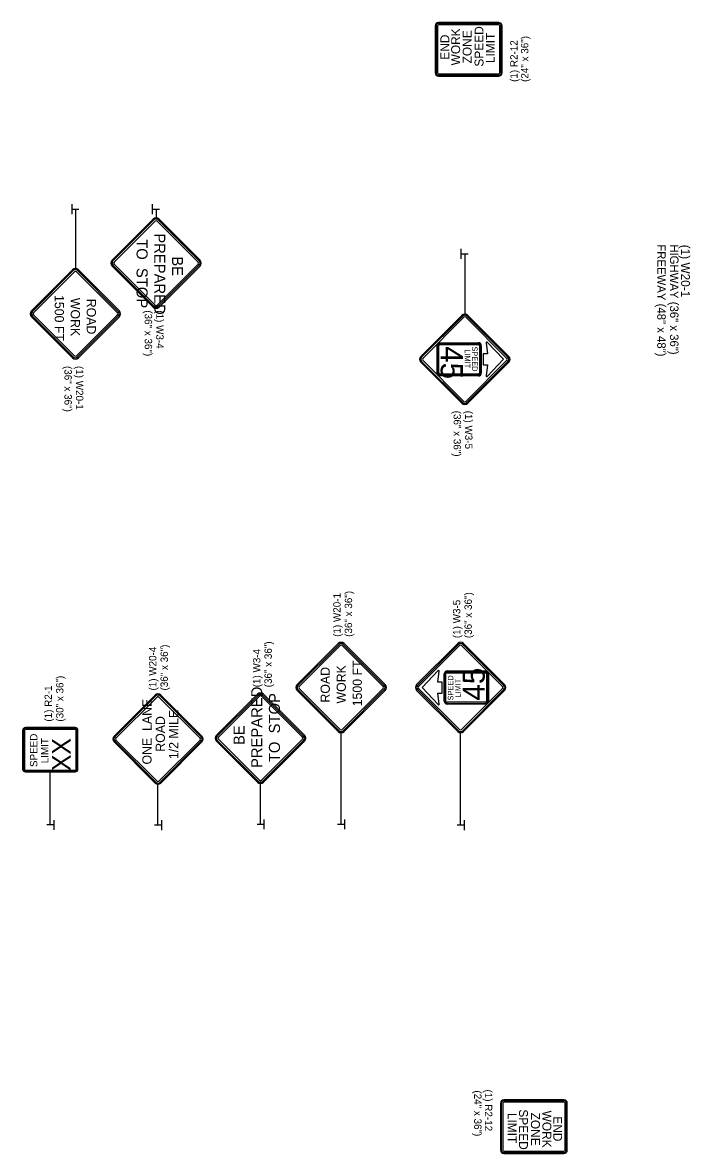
# Model space of a CAD drawing. Extents: x 1925873 to 1930787, y 596452 to 599617.
# Drawn here: x 1927188 to 1927732, y 598697 to 599617 of the extents above; entities that cross this region are included whole.
import ezdxf

# ---------------------------------------------------------------- set-up
doc = ezdxf.new("R2010")
doc.units = 0
for name, color, linetype in [('Default', 7, 'Continuous'), ('P_TC_Signs_Permanent', 7, 'Continuous'), ('P_TC_Signs_Temporary', 7, 'Continuous'), ('R_Border', 7, 'Continuous')]:
    doc.layers.add(name, color=color, linetype=linetype)

msp = doc.modelspace()

# ---------------------------------------------------------------- linework, layer by layer
at = {"layer": 'Default'}
for p, q in [((1927228.46, 599461.2), (1927228.46, 599469.2)), ((1927293.94, 599461.2), (1927293.94, 599469.2)), ((1927228.57, 599465.18), (1927234.04, 599465.18)), ((1927294.05, 599465.18), (1927299.52, 599465.18)), ((1927545.18, 599424.79), (1927545.18, 599432.79)), ((1927545.29, 599428.77), (1927550.76, 599428.77)), ((1927384.59, 598968.57), (1927384.59, 598960.56)), ((1927450.07, 598968.57), (1927450.07, 598960.56)), ((1927213.4, 598964.08), (1927207.93, 598964.08)), ((1927213.52, 598968.06), (1927213.52, 598960.05)), ((1927301.07, 598963.91), (1927295.6, 598963.91)), ((1927301.18, 598967.89), (1927301.18, 598959.89)), ((1927384.47, 598964.59), (1927379.01, 598964.59)), ((1927449.95, 598964.59), (1927444.49, 598964.59)), ((1927547.35, 598963.96), (1927541.88, 598963.96)), ((1927547.46, 598967.94), (1927547.46, 598959.93))]:
    msp.add_line(p, q, dxfattribs=at)
at = {"layer": 'P_TC_Signs_Permanent'}
for p, q in [((1927523.95, 599614.27), (1927523.95, 599576.2)), ((1927524.63, 599614.27), (1927524.63, 599576.2)), ((1927525.76, 599614.27), (1927525.76, 599576.2)), ((1927575.6, 599616.99), (1927526.67, 599616.99)), ((1927575.6, 599616.31), (1927526.67, 599616.31)), ((1927575.6, 599615.17), (1927526.67, 599615.17)), ((1927576.51, 599576.2), (1927576.51, 599614.27)), ((1927577.64, 599576.2), (1927577.64, 599614.27)), ((1927578.32, 599576.2), (1927578.32, 599614.27)), ((1927526.67, 599575.3), (1927575.6, 599575.3)), ((1927526.67, 599574.17), (1927575.6, 599574.17)), ((1927526.67, 599573.49), (1927575.6, 599573.49)), ((1927294.4, 599457.08), (1927260.99, 599423.67)), ((1927295.06, 599456.42), (1927261.65, 599423.01)), ((1927331.92, 599423.01), (1927298.51, 599456.42)), ((1927332.58, 599423.67), (1927299.17, 599457.08)), ((1927295.99, 599455.49), (1927262.58, 599422.08)), ((1927330.99, 599422.08), (1927297.58, 599455.49)), ((1927261.65, 599419.56), (1927295.06, 599386.15)), ((1927262.58, 599420.49), (1927295.99, 599387.08)), ((1927297.58, 599387.08), (1927330.99, 599420.49)), ((1927298.51, 599386.15), (1927331.92, 599419.56)), ((1927260.99, 599418.89), (1927294.4, 599385.48)), ((1927299.17, 599385.48), (1927332.58, 599418.89)), ((1927545.64, 599378.79), (1927512.23, 599345.38)), ((1927546.3, 599378.13), (1927512.89, 599344.72)), ((1927547.23, 599377.2), (1927513.82, 599343.79)), ((1927582.23, 599343.79), (1927548.82, 599377.2)), ((1927583.16, 599344.72), (1927549.75, 599378.13)), ((1927583.82, 599345.38), (1927550.41, 599378.79)), ((1927527.83, 599356.49), (1927559.03, 599356.49)), ((1927525.43, 599331.89), (1927525.43, 599354.09)), ((1927561.43, 599354.09), (1927561.43, 599331.89)), ((1927512.23, 599340.61), (1927545.64, 599307.2)), ((1927512.89, 599341.27), (1927546.3, 599307.86)), ((1927513.82, 599342.2), (1927547.23, 599308.79)), ((1927548.82, 599308.79), (1927582.23, 599342.2)), ((1927549.75, 599307.86), (1927583.16, 599341.27)), ((1927550.41, 599307.2), (1927583.82, 599340.61)), ((1927559.03, 599329.49), (1927527.83, 599329.49)), ((1927542.23, 599111.72), (1927508.82, 599078.31)), ((1927542.89, 599111.06), (1927509.48, 599077.65)), ((1927543.82, 599110.13), (1927510.41, 599076.72)), ((1927578.82, 599076.72), (1927545.41, 599110.13)), ((1927579.75, 599077.65), (1927546.34, 599111.06)), ((1927580.41, 599078.31), (1927547, 599111.72)), ((1927533.61, 599089.43), (1927564.81, 599089.43)), ((1927531.21, 599064.83), (1927531.21, 599087.03)), ((1927567.21, 599087.03), (1927567.21, 599064.83)), ((1927379.35, 599070.48), (1927345.94, 599037.06)), ((1927380.02, 599069.81), (1927346.6, 599036.4)), ((1927416.87, 599036.4), (1927383.46, 599069.81)), ((1927417.54, 599037.06), (1927384.13, 599070.48)), ((1927508.82, 599073.54), (1927542.23, 599040.13)), ((1927509.48, 599074.2), (1927542.89, 599040.79)), ((1927510.41, 599075.13), (1927543.82, 599041.72)), ((1927545.41, 599041.72), (1927578.82, 599075.13)), ((1927546.34, 599040.79), (1927579.75, 599074.2)), ((1927547, 599040.13), (1927580.41, 599073.54)), ((1927380.94, 599068.88), (1927347.53, 599035.47)), ((1927415.95, 599035.47), (1927382.53, 599068.88)), ((1927564.81, 599062.43), (1927533.61, 599062.43)), ((1927230.92, 599043.3), (1927190.42, 599043.3)), ((1927230.92, 599042.73), (1927190.42, 599042.73)), ((1927188.17, 599041.05), (1927188.17, 599009.55)), ((1927188.73, 599041.05), (1927188.73, 599009.55)), ((1927189.67, 599041.05), (1927189.67, 599009.55)), ((1927230.92, 599041.8), (1927190.42, 599041.8)), ((1927231.67, 599009.55), (1927231.67, 599041.05)), ((1927232.6, 599009.55), (1927232.6, 599041.05)), ((1927233.17, 599009.55), (1927233.17, 599041.05)), ((1927346.6, 599032.95), (1927380.02, 598999.54)), ((1927347.53, 599033.88), (1927380.94, 599000.47)), ((1927382.53, 599000.47), (1927415.95, 599033.88)), ((1927383.46, 598999.54), (1927416.87, 599032.95)), ((1927345.94, 599032.29), (1927379.35, 598998.88)), ((1927384.13, 598998.88), (1927417.54, 599032.29)), ((1927190.42, 599008.8), (1927230.92, 599008.8)), ((1927190.42, 599007.86), (1927230.92, 599007.86)), ((1927190.42, 599007.3), (1927230.92, 599007.3)), ((1927628.69, 598740.35), (1927579.75, 598740.35)), ((1927628.69, 598739.67), (1927579.75, 598739.67)), ((1927628.69, 598738.54), (1927579.75, 598738.54)), ((1927577.03, 598737.64), (1927577.03, 598699.57)), ((1927577.71, 598737.64), (1927577.71, 598699.57)), ((1927578.84, 598737.64), (1927578.84, 598699.57)), ((1927629.59, 598699.57), (1927629.59, 598737.64)), ((1927630.73, 598699.57), (1927630.73, 598737.64)), ((1927631.41, 598699.57), (1927631.41, 598737.64)), ((1927579.75, 598698.67), (1927628.69, 598698.67)), ((1927579.75, 598697.53), (1927628.69, 598697.53)), ((1927579.75, 598696.85), (1927628.69, 598696.85))]:
    msp.add_line(p, q, dxfattribs=at)
for points in [[(1927559.03, 599355.89), (1927527.83, 599355.89)], [(1927527.83, 599354.99), (1927559.03, 599354.99)], [(1927565.38, 599356.45), (1927566.5, 599347.49), (1927562.93, 599347.49), (1927562.93, 599338.49), (1927566.49, 599338.49), (1927565.38, 599329.61)], [(1927566.35, 599329.15), (1927579.43, 599343.03), (1927566.35, 599356.91)], [(1927526.03, 599354.09), (1927526.03, 599331.89)], [(1927526.93, 599331.89), (1927526.93, 599354.09)], [(1927559.93, 599354.09), (1927559.93, 599342.99), (1927559.93, 599331.89)], [(1927560.83, 599331.89), (1927560.83, 599342.99), (1927560.83, 599354.09)], [(1927559.03, 599330.99), (1927527.83, 599330.99)], [(1927527.83, 599330.09), (1927559.03, 599330.09)], [(1927526.29, 599089.77), (1927513.21, 599075.89), (1927526.29, 599062.01)], [(1927527.26, 599062.46), (1927526.14, 599071.43), (1927529.71, 599071.43), (1927529.71, 599080.43), (1927526.15, 599080.43), (1927527.26, 599089.31)], [(1927564.81, 599088.83), (1927533.61, 599088.83)], [(1927531.81, 599087.03), (1927531.81, 599075.93), (1927531.81, 599064.83)], [(1927532.71, 599064.83), (1927532.71, 599075.93), (1927532.71, 599087.03)], [(1927533.61, 599087.93), (1927564.81, 599087.93)], [(1927565.71, 599087.03), (1927565.71, 599064.83)], [(1927566.61, 599064.83), (1927566.61, 599087.03)], [(1927564.81, 599063.93), (1927533.61, 599063.93)], [(1927533.61, 599063.03), (1927564.81, 599063.03)]]:
    msp.add_lwpolyline(points, dxfattribs=at)
for centre, radius, start, end in [((1927526.67, 599614.27), 2.72, 90, 180), ((1927526.67, 599614.27), 2.04, 90, 180), ((1927526.67, 599614.27), 0.906, 90, 180), ((1927575.6, 599614.27), 2.72, 360, 90), ((1927575.6, 599614.27), 2.04, 360, 90), ((1927575.6, 599614.27), 0.906, 360, 90), ((1927526.67, 599576.2), 2.72, 180, 270), ((1927526.67, 599576.2), 2.04, 180, 270), ((1927526.67, 599576.2), 0.906, 180, 270), ((1927575.6, 599576.2), 2.72, 270, 360), ((1927575.6, 599576.2), 2.04, 270, 360), ((1927575.6, 599576.2), 0.906, 270, 360), ((1927296.79, 599454.69), 3.37, 45, 135), ((1927296.79, 599454.69), 2.44, 45, 135), ((1927296.79, 599454.69), 1.13, 45, 135), ((1927263.38, 599421.28), 3.37, 135, 225), ((1927263.38, 599421.28), 2.44, 135, 225), ((1927263.38, 599421.28), 1.13, 135, 225), ((1927330.2, 599421.28), 1.13, 315, 45), ((1927330.2, 599421.28), 2.44, 315, 45), ((1927330.2, 599421.28), 3.37, 315, 45), ((1927296.79, 599387.87), 3.37, 225, 315), ((1927296.79, 599387.87), 2.44, 225, 315), ((1927296.79, 599387.87), 1.13, 225, 315), ((1927548.03, 599376.4), 3.37, 45, 135), ((1927548.03, 599376.4), 2.44, 45, 135), ((1927548.03, 599376.4), 1.13, 45, 135), ((1927527.83, 599354.09), 2.4, 90, 180), ((1927527.83, 599354.09), 1.8, 90, 180), ((1927527.83, 599354.09), 0.9, 90, 180), ((1927559.03, 599354.09), 2.4, 360, 90), ((1927559.03, 599354.09), 1.8, 360, 90), ((1927559.03, 599354.09), 0.9, 360, 90), ((1927565.94, 599356.52), 0.563, 43.31166, 187.12501), ((1927514.62, 599342.99), 3.37, 135, 225), ((1927514.62, 599342.99), 2.44, 135, 225), ((1927514.62, 599342.99), 1.13, 135, 225), ((1927581.44, 599342.99), 1.13, 315, 45), ((1927581.44, 599342.99), 2.44, 315, 45), ((1927581.44, 599342.99), 3.37, 315, 45), ((1927527.83, 599331.89), 2.4, 180, 270), ((1927527.83, 599331.89), 1.8, 180, 270), ((1927527.83, 599331.89), 0.9, 180, 270), ((1927559.03, 599331.89), 2.4, 270, 360), ((1927559.03, 599331.89), 1.8, 270, 360), ((1927559.03, 599331.89), 0.9, 270, 360), ((1927565.94, 599329.54), 0.563, 172.87498, 316.68834), ((1927548.03, 599309.58), 3.38, 225, 315), ((1927548.03, 599309.58), 2.44, 225, 315), ((1927548.03, 599309.58), 1.13, 225, 315), ((1927544.61, 599109.34), 3.37, 45, 135), ((1927544.61, 599109.34), 2.44, 45, 135), ((1927544.61, 599109.34), 1.13, 45, 135), ((1927526.7, 599089.38), 0.563, 352.87498, 136.68834), ((1927533.61, 599087.03), 2.4, 90, 180), ((1927533.61, 599087.03), 1.8, 90, 180), ((1927564.81, 599087.03), 2.4, 360, 90), ((1927564.81, 599087.03), 1.8, 360, 90), ((1927533.61, 599087.03), 0.9, 90, 180), ((1927564.81, 599087.03), 0.9, 360, 90), ((1927381.74, 599068.09), 3.37, 45, 135), ((1927381.74, 599068.09), 2.44, 45, 135), ((1927511.2, 599075.93), 3.37, 135, 225), ((1927511.2, 599075.93), 2.44, 135, 225), ((1927511.2, 599075.93), 1.13, 135, 225), ((1927578.02, 599075.93), 1.13, 315, 45), ((1927578.02, 599075.93), 2.44, 315, 45), ((1927578.02, 599075.93), 3.37, 315, 45), ((1927381.74, 599068.09), 1.13, 45, 135), ((1927526.7, 599062.39), 0.563, 223.31166, 7.12501), ((1927533.61, 599064.83), 2.4, 180, 270), ((1927533.61, 599064.83), 1.8, 180, 270), ((1927533.61, 599064.83), 0.9, 180, 270), ((1927564.81, 599064.83), 2.4, 270, 360), ((1927564.81, 599064.83), 1.8, 270, 360), ((1927564.81, 599064.83), 0.9, 270, 360), ((1927190.42, 599041.05), 2.25, 90, 180), ((1927190.42, 599041.05), 1.69, 90, 180), ((1927230.92, 599041.05), 2.25, 360, 90), ((1927230.92, 599041.05), 1.69, 360, 90), ((1927190.42, 599041.05), 0.75, 90, 180), ((1927230.92, 599041.05), 0.75, 360, 90), ((1927348.33, 599034.68), 3.37, 135, 225), ((1927348.33, 599034.68), 2.44, 135, 225), ((1927348.33, 599034.68), 1.13, 135, 225), ((1927415.15, 599034.68), 1.13, 315, 45), ((1927415.15, 599034.68), 2.44, 315, 45), ((1927415.15, 599034.68), 3.37, 315, 45), ((1927544.61, 599042.51), 3.37, 225, 315), ((1927544.61, 599042.51), 2.44, 225, 315), ((1927544.61, 599042.51), 1.13, 225, 315), ((1927190.42, 599009.55), 2.25, 180, 270), ((1927190.42, 599009.55), 1.69, 180, 270), ((1927190.42, 599009.55), 0.75, 180, 270), ((1927230.92, 599009.55), 2.25, 270, 360), ((1927230.92, 599009.55), 1.69, 270, 360), ((1927230.92, 599009.55), 0.75, 270, 360), ((1927381.74, 599001.27), 3.37, 225, 315), ((1927381.74, 599001.27), 2.44, 225, 315), ((1927381.74, 599001.27), 1.13, 225, 315), ((1927579.75, 598737.64), 2.72, 90, 180), ((1927579.75, 598737.64), 2.04, 90, 180), ((1927579.75, 598737.64), 0.906, 90, 180), ((1927628.69, 598737.64), 2.72, 360, 90), ((1927628.69, 598737.64), 2.04, 360, 90), ((1927628.69, 598737.64), 0.906, 360, 90), ((1927579.75, 598699.57), 2.72, 180, 270), ((1927579.75, 598699.57), 2.04, 180, 270), ((1927579.75, 598699.57), 0.906, 180, 270), ((1927628.69, 598699.57), 2.72, 270, 360), ((1927628.69, 598699.57), 2.04, 270, 360), ((1927628.69, 598699.57), 0.906, 270, 360)]:
    msp.add_arc(centre, radius, start, end, dxfattribs=at)
at = {"layer": 'P_TC_Signs_Temporary'}
for p, q in [((1927195.34, 599382.42), (1927228.75, 599415.83)), ((1927196, 599381.76), (1927229.41, 599415.17)), ((1927196.93, 599380.83), (1927230.34, 599414.24)), ((1927231.93, 599414.24), (1927265.34, 599380.83)), ((1927232.86, 599415.17), (1927266.27, 599381.76)), ((1927233.52, 599415.83), (1927266.93, 599382.42)), ((1927228.75, 599344.24), (1927195.34, 599377.65)), ((1927229.41, 599344.9), (1927196, 599378.31)), ((1927230.34, 599345.83), (1927196.93, 599379.24)), ((1927265.34, 599379.24), (1927231.93, 599345.83)), ((1927266.27, 599378.31), (1927232.86, 599344.9)), ((1927266.93, 599377.65), (1927233.52, 599344.24)), ((1927411.59, 599078.31), (1927445.01, 599111.72)), ((1927412.26, 599077.65), (1927445.67, 599111.06)), ((1927413.19, 599076.72), (1927446.6, 599110.13)), ((1927448.19, 599110.13), (1927481.6, 599076.72)), ((1927449.12, 599111.06), (1927482.53, 599077.65)), ((1927449.78, 599111.72), (1927483.19, 599078.31)), ((1927262.54, 599036.39), (1927295.95, 599069.8)), ((1927300.72, 599069.8), (1927334.13, 599036.39)), ((1927445.01, 599040.13), (1927411.59, 599073.54)), ((1927445.67, 599040.79), (1927412.26, 599074.2)), ((1927446.6, 599041.72), (1927413.19, 599075.13)), ((1927481.6, 599075.13), (1927448.19, 599041.72)), ((1927482.53, 599074.2), (1927449.12, 599040.79)), ((1927483.19, 599073.54), (1927449.78, 599040.13)), ((1927263.2, 599035.73), (1927296.61, 599069.14)), ((1927264.13, 599034.8), (1927297.54, 599068.21)), ((1927299.13, 599068.21), (1927332.54, 599034.8)), ((1927300.06, 599069.14), (1927333.47, 599035.73)), ((1927297.54, 598999.8), (1927264.13, 599033.21)), ((1927332.54, 599033.21), (1927299.13, 598999.8)), ((1927295.95, 598998.2), (1927262.54, 599031.62)), ((1927296.61, 598998.87), (1927263.2, 599032.28)), ((1927333.47, 599032.28), (1927300.06, 598998.87)), ((1927334.13, 599031.62), (1927300.72, 598998.2))]:
    msp.add_line(p, q, dxfattribs=at)
for centre, radius, start, end in [((1927231.13, 599413.45), 3.37, 45, 135), ((1927231.13, 599413.45), 2.44, 45, 135), ((1927231.13, 599413.45), 1.12, 45, 135), ((1927197.72, 599380.04), 3.37, 135, 225), ((1927197.72, 599380.04), 2.44, 135, 225), ((1927197.72, 599380.04), 1.13, 135, 225), ((1927264.54, 599380.04), 1.13, 315, 45), ((1927264.54, 599380.04), 2.44, 315, 45), ((1927264.54, 599380.04), 3.37, 315, 45), ((1927231.13, 599346.63), 1.12, 225, 315), ((1927231.13, 599346.63), 3.37, 225, 315), ((1927231.13, 599346.63), 2.44, 225, 315), ((1927447.39, 599109.33), 3.37, 45, 135), ((1927447.39, 599109.33), 2.44, 45, 135), ((1927447.39, 599109.33), 1.12, 45, 135), ((1927298.33, 599067.41), 3.37, 45, 135), ((1927298.33, 599067.41), 2.44, 45, 135), ((1927413.98, 599075.92), 3.37, 135, 225), ((1927413.98, 599075.92), 2.44, 135, 225), ((1927413.98, 599075.92), 1.13, 135, 225), ((1927480.8, 599075.92), 1.13, 315, 45), ((1927480.8, 599075.92), 2.44, 315, 45), ((1927480.8, 599075.92), 3.37, 315, 45), ((1927298.33, 599067.41), 1.12, 45, 135), ((1927264.92, 599034), 3.37, 135, 225), ((1927264.92, 599034), 2.44, 135, 225), ((1927264.92, 599034), 1.13, 135, 225), ((1927331.75, 599034), 1.13, 315, 45), ((1927331.75, 599034), 2.44, 315, 45), ((1927331.75, 599034), 3.37, 315, 45), ((1927447.39, 599042.51), 3.37, 225, 315), ((1927447.39, 599042.51), 2.44, 225, 315), ((1927447.39, 599042.51), 1.12, 225, 315), ((1927298.33, 599000.59), 3.37, 225, 315), ((1927298.33, 599000.59), 2.44, 225, 315), ((1927298.33, 599000.59), 1.12, 225, 315)]:
    msp.add_arc(centre, radius, start, end, dxfattribs=at)
at = {"layer": 'R_Border'}
for p, q in [((1927231.13, 599465.18), (1927231.13, 599416.82)), ((1927296.79, 599465.18), (1927296.79, 599458.07)), ((1927548.03, 599428.77), (1927548.03, 599379.78)), ((1927447.39, 598964.59), (1927447.39, 599039.14)), ((1927544.61, 598963.96), (1927544.61, 599039.14)), ((1927210.67, 598964.08), (1927210.67, 599007.3)), ((1927298.33, 598963.91), (1927298.33, 598997.22)), ((1927381.74, 598964.59), (1927381.74, 598997.89))]:
    msp.add_line(p, q, dxfattribs=at)

# ---------------------------------------------------------------- texts
at = {"layer": 'P_TC_Signs_Permanent'}
for s, height, rotation, p in [('SPEED', 7.251, 90, (1927563.21, 599581.17)), ('END', 7.251, 90, (1927535.36, 599586.78)), ('WORK', 7.251, 90, (1927544.18, 599582.18)), ('ZONE', 7.251, 90, (1927553.53, 599583.8)), ('LIMIT', 7.251, 90, (1927572.43, 599584.01)), ('45', 18, 270, (1927528.43, 599353.67)), ('LIMIT', 4.5, 270, (1927547.93, 599351.18)), ('SPEED', 4.5, 270, (1927553.93, 599353.49)), ('45', 18, 90, (1927564.21, 599065.25)), ('SPEED', 4.5, 90, (1927538.71, 599065.43)), ('LIMIT', 4.5, 90, (1927544.71, 599067.74)), ('SPEED', 6, 90, (1927200.17, 599011.23)), ('LIMIT', 6, 90, (1927209.17, 599014.32)), ('XX', 15, 90, (1927227.17, 599008)), ('SPEED', 7.251, 270, (1927592.14, 598732.67)), ('ZONE', 7.251, 270, (1927601.83, 598730.04)), ('WORK', 7.251, 270, (1927611.18, 598731.66)), ('LIMIT', 7.251, 270, (1927582.92, 598729.83)), ('END', 7.251, 270, (1927619.99, 598727.06))]:
    msp.add_text(s, height=height, rotation=rotation, dxfattribs=at).set_placement(p)
at = {"layer": 'P_TC_Signs_Temporary'}
for s, height, rotation, p in [('TO  STOP', 9, 270, (1927280.91, 599440.75)), ('PREPARED', 9, 270, (1927295.31, 599445.52)), ('BE', 9, 270, (1927309.71, 599426.83)), ('1500 FT', 7.5, 270, (1927214.3, 599395.33)), ('WORK', 7.5, 270, (1927227.32, 599393.03)), (' ROAD ', 7.5, 270, (1927240.35, 599395.06)), ('1500 FT', 7.5, 90, (1927464.23, 599060.63)), (' ROAD ', 7.5, 90, (1927438.18, 599060.9)), ('WORK', 7.5, 90, (1927451.2, 599062.93)), ('PREPARED', 9, 90, (1927383.21, 599010.44)), ('TO  STOP', 9, 90, (1927397.61, 599015.21)), ('ONE  LANE', 7.5, 90, (1927293.08, 599013.3)), ('ROAD', 7.5, 90, (1927303.96, 599023.7)), ('1/2 MILE', 7.5, 90, (1927314.83, 599017.69)), ('BE', 9, 90, (1927368.81, 599029.13))]:
    msp.add_text(s, height=height, rotation=rotation, dxfattribs=at).set_placement(p)
at = {"layer": 'R_Border'}
for s, height, rotation, p in [('(24" x 36")', 5.9996, 90, (1927599.73, 599568.75)), ('(1) R2-12', 6, 90, (1927590.98, 599568.75)), ('FREEWAY (48" x 48")', 6.912, 270, (1927704.62, 599436.61)), ('HIGHWAY (36" x 36")', 6.912, 270, (1927714.99, 599436.61)), ('(1) W20-1', 7.2, 270, (1927724.01, 599436.25)), ('(36" x 36")', 5.9996, 270, (1927287.55, 599382.88)), ('(1) W3-4', 6, 270, (1927296.92, 599382.88)), ('(36" x 36")', 5.9996, 270, (1927222.21, 599337.6)), ('(1) W20-1', 6, 270, (1927231.57, 599337.6)), ('(36" x 36")', 5.9996, 270, (1927538.9, 599301.19)), ('(1) W3-5', 6, 270, (1927548.26, 599301.19)), ('(36" x 36")', 5.9996, 90, (1927456.31, 599117.19)), ('(36" x 36")', 6, 90, (1927553.74, 599116.12)), ('(1) W20-1', 6, 90, (1927446.95, 599117.19)), ('(1) W3-5', 6, 90, (1927544.38, 599116.12)), ('(1) W20-4', 6, 90, (1927297.02, 599073.51)), ('(36" x 36")', 6, 90, (1927306.38, 599073.51)), ('(1) W3-4', 6, 90, (1927381.61, 599076.12)), ('(36" x 36")', 5.9996, 90, (1927390.97, 599076.12)), ('(30" x 36")', 5.9996, 90, (1927221.38, 599048.18)), ('(1) R2-1', 6, 90, (1927212.02, 599048.18)), ('(1) R2-12', 6, 270, (1927564.38, 598748.83)), ('(24" x 36")', 5.9996, 270, (1927555.63, 598748.09))]:
    msp.add_text(s, height=height, rotation=rotation, dxfattribs=at).set_placement(p)

doc.saveas('drawing.dxf')
